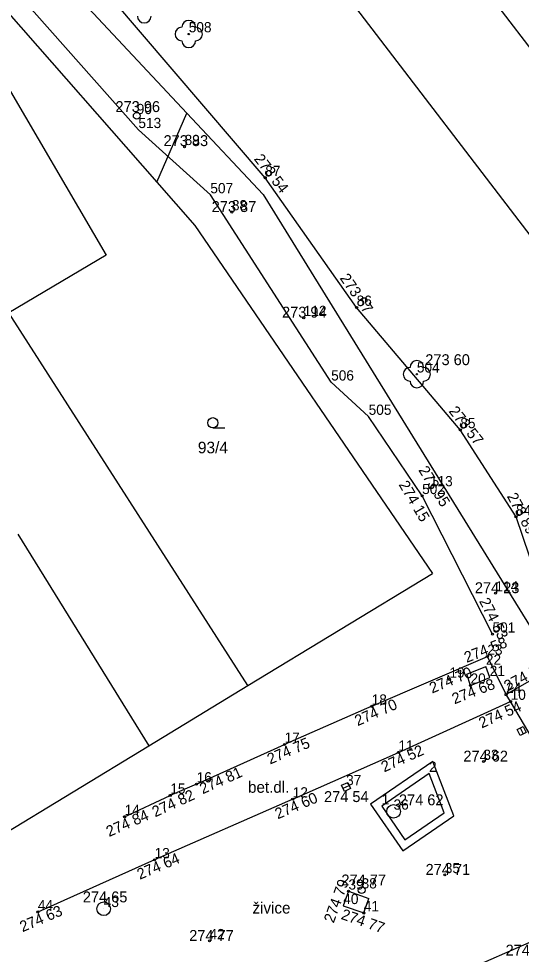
# Model space of a CAD drawing. Extents: x -492379 to -491966, y -1126153 to -1125860.
# Drawn here: x -492207.01 to -492184.88, y -1126038.78 to -1125997.58 of the extents above; entities that cross this region are included whole.
import ezdxf

# ---------------------------------------------------------------- set-up
doc = ezdxf.new("R2010")
doc.units = 0
for name, color, linetype in [('body', 7, 'Continuous'), ('hrana svahu', 7, 'Continuous'), ('kanalizace', 7, 'Continuous'), ('katastrální mapa', 7, 'Continuous'), ('ostatní objekty', 7, 'Continuous'), ('plot', 7, 'Continuous'), ('plyn', 7, 'Continuous'), ('podrobný výškový bod', 7, 'Continuous'), ('popis ploch', 7, 'Continuous'), ('rozhraní ploch', 7, 'Continuous'), ('silové vedení', 7, 'Continuous'), ('vodovod', 7, 'Continuous'), ('vstup na pozemek', 7, 'Continuous'), ('výšky', 7, 'Continuous'), ('čísla bodů', 7, 'Continuous')]:
    doc.layers.add(name, color=color, linetype=linetype)

msp = doc.modelspace()

# ---------------------------------------------------------------- linework, layer by layer
at = {"layer": 'body'}
for p, q in [((-492199.521, -1125998.258), (-492199.521, -1125998.258)), ((-492201.81, -1126001.858), (-492201.81, -1126001.858)), ((-492201.739, -1126002.474), (-492201.739, -1126002.474)), ((-492199.703, -1126003.222), (-492199.703, -1126003.222)), ((-492196.15, -1126004.585), (-492196.15, -1126004.585)), ((-492198.57, -1126005.345), (-492198.57, -1126005.345)), ((-492197.621, -1126006.096), (-492197.621, -1126006.096)), ((-492192.127, -1126010.3), (-492192.127, -1126010.3)), ((-492194.458, -1126010.749), (-492194.458, -1126010.749)), ((-492189.476, -1126013.237), (-492189.476, -1126013.237)), ((-492193.25, -1126013.59), (-492193.25, -1126013.59)), ((-492191.598, -1126015.101), (-492191.598, -1126015.101)), ((-492187.562, -1126015.688), (-492187.562, -1126015.688)), ((-492188.9, -1126018.244), (-492188.9, -1126018.244)), ((-492189.244, -1126018.589), (-492189.244, -1126018.589)), ((-492185.109, -1126019.52), (-492185.109, -1126019.52)), ((-492186.014, -1126022.877), (-492186.014, -1126022.877)), ((-492186.144, -1126024.687), (-492186.144, -1126024.687)), ((-492186.372, -1126025.666), (-492186.372, -1126025.666)), ((-492186.436, -1126026.104), (-492186.436, -1126026.104)), ((-492188.042, -1126026.672), (-492188.042, -1126026.672)), ((-492186.267, -1126026.598), (-492186.267, -1126026.598)), ((-492187.113, -1126026.937), (-492187.113, -1126026.937)), ((-492185.549, -1126027.345), (-492185.549, -1126027.345)), ((-492191.463, -1126027.86), (-492191.463, -1126027.86)), ((-492185.346, -1126027.649), (-492185.346, -1126027.649)), ((-492195.302, -1126029.538), (-492195.302, -1126029.538)), ((-492190.287, -1126029.887), (-492190.287, -1126029.887)), ((-492186.545, -1126030.293), (-492186.545, -1126030.293)), ((-492188.938, -1126030.823), (-492188.938, -1126030.823)), ((-492199.175, -1126031.285), (-492199.175, -1126031.285)), ((-492192.591, -1126031.407), (-492192.591, -1126031.407)), ((-492200.334, -1126031.781), (-492200.334, -1126031.781)), ((-492194.943, -1126031.947), (-492194.943, -1126031.947)), ((-492191.025, -1126032.254), (-492191.025, -1126032.254)), ((-492202.345, -1126032.721), (-492202.345, -1126032.721)), ((-492190.503, -1126032.485), (-492190.503, -1126032.485)), ((-492201.024, -1126034.624), (-492201.024, -1126034.624)), ((-492188.245, -1126035.281), (-492188.245, -1126035.281)), ((-492192.488, -1126036.005), (-492192.488, -1126036.005)), ((-492191.908, -1126035.954), (-492191.908, -1126035.954)), ((-492206.166, -1126036.917), (-492206.166, -1126036.917)), ((-492203.265, -1126036.774), (-492203.265, -1126036.774)), ((-492192.717, -1126036.642), (-492192.717, -1126036.642)), ((-492191.812, -1126036.96), (-492191.812, -1126036.96)), ((-492198.61, -1126038.189), (-492198.61, -1126038.189))]:
    msp.add_line(p, q, dxfattribs=at)
at = {"layer": 'hrana svahu'}
for p, q in [((-492196.15, -1126004.585), (-492205.259, -1125993.96)), ((-492192.127, -1126010.3), (-492196.15, -1126004.585)), ((-492187.562, -1126015.688), (-492192.127, -1126010.3)), ((-492185.109, -1126019.52), (-492187.562, -1126015.688)), ((-492183.695, -1126023.691), (-492185.109, -1126019.52))]:
    msp.add_line(p, q, dxfattribs=at)
at = {"layer": 'kanalizace'}
for p, q in [((-492184.929, -1126028.814), (-492184.787, -1126029.078)), ((-492192.728, -1126031.468), (-492192.454, -1126031.346))]:
    msp.add_line(p, q, dxfattribs=at)
for points in [[(-492184.797, -1126028.743), (-492184.655, -1126029.008), (-492184.92, -1126029.149), (-492185.062, -1126028.885)], [(-492192.789, -1126031.331), (-492192.515, -1126031.209), (-492192.393, -1126031.483), (-492192.667, -1126031.605)]]:
    msp.add_lwpolyline(points, close=True, dxfattribs=at)
for centre in [(-492190.503, -1126032.485), (-492203.265, -1126036.774)]:
    msp.add_circle(centre, 0.3, dxfattribs=at)
at = {"layer": 'katastrální mapa'}
for p, q in [((-492216.8, -1125983.38), (-492199.61, -1126001.74)), ((-492194.65, -1125985.54), (-492177.26, -1126008.38)), ((-492198.1, -1125989.34), (-492176.36, -1126017.77)), ((-492207.54, -1125997.23), (-492200.93, -1126004.78)), ((-492208.65, -1125998.64), (-492203.15, -1126007.99)), ((-492200.93, -1126004.78), (-492199.61, -1126001.74)), ((-492199.61, -1126001.74), (-492196.25, -1126005.33)), ((-492200.93, -1126004.78), (-492199.25, -1126006.69)), ((-492196.25, -1126005.33), (-492184.32, -1126024.61)), ((-492199.25, -1126006.69), (-492188.79, -1126022.01)), ((-492203.15, -1126007.99), (-492207.44, -1126010.54)), ((-492196.92, -1126026.95), (-492207.44, -1126010.54)), ((-492198.46, -1126015.6), (-492197.93, -1126015.6)), ((-492207.05, -1126020.28), (-492201.28, -1126029.6)), ((-492196.92, -1126026.95), (-492188.79, -1126022.01)), ((-492201.28, -1126029.6), (-492196.92, -1126026.95)), ((-492212.92, -1126036.68), (-492201.28, -1126029.6)), ((-492191.74, -1126041.4), (-492182.01, -1126037.16))]:
    msp.add_line(p, q, dxfattribs=at)
msp.add_circle((-492198.46, -1126015.375), 0.225, dxfattribs=at)
at = {"layer": 'ostatní objekty'}
for p, q in [((-492188.77, -1126030.283), (-492191.512, -1126032.163)), ((-492187.851, -1126032.684), (-492188.77, -1126030.283)), ((-492188.938, -1126030.823), (-492191.025, -1126032.254)), ((-492188.277, -1126032.551), (-492188.938, -1126030.823)), ((-492191.512, -1126032.163), (-492190.098, -1126034.225)), ((-492191.025, -1126032.254), (-492190.007, -1126033.738)), ((-492190.098, -1126034.225), (-492187.851, -1126032.684)), ((-492190.007, -1126033.738), (-492188.277, -1126032.551))]:
    msp.add_line(p, q, dxfattribs=at)
for centre in [(-492199.521, -1125998.258), (-492189.476, -1126013.237)]:
    msp.add_circle(centre, 0.03, dxfattribs=at)
for centre, start, end in [((-492201.482, -1125997.469), 180, 0), ((-492199.521, -1125997.958), 0, 180), ((-492199.821, -1125998.258), 90, 270), ((-492199.221, -1125998.258), 270, 90), ((-492199.521, -1125998.558), 180, 0), ((-492189.476, -1126012.937), 0, 180), ((-492189.776, -1126013.237), 90, 270), ((-492189.176, -1126013.237), 270, 90), ((-492189.476, -1126013.537), 180, 0)]:
    msp.add_arc(centre, 0.3, start, end, dxfattribs=at)
at = {"layer": 'plot'}
for p, q in [((-492201.739, -1126002.474), (-492206.915, -1125996.619)), ((-492198.57, -1126005.345), (-492201.739, -1126002.474)), ((-492193.25, -1126013.59), (-492198.57, -1126005.345)), ((-492191.598, -1126015.101), (-492193.25, -1126013.59)), ((-492189.244, -1126018.589), (-492191.598, -1126015.101)), ((-492186.144, -1126024.687), (-492189.244, -1126018.589)), ((-492191.463, -1126027.86), (-492186.372, -1126025.666)), ((-492199.175, -1126031.285), (-492195.302, -1126029.538)), ((-492202.345, -1126032.721), (-492200.334, -1126031.781))]:
    msp.add_line(p, q, dxfattribs=at)
at = {"layer": 'plyn'}
msp.add_circle((-492201.81, -1126001.858), 0.15, dxfattribs=at)
at = {"layer": 'podrobný výškový bod'}
for centre in [(-492199.703, -1126003.222), (-492196.15, -1126004.585), (-492197.621, -1126006.096), (-492192.127, -1126010.3), (-492194.458, -1126010.749), (-492187.562, -1126015.688), (-492188.9, -1126018.244), (-492189.244, -1126018.589), (-492185.109, -1126019.52), (-492186.014, -1126022.877), (-492186.144, -1126024.687), (-492186.372, -1126025.666), (-492188.042, -1126026.672), (-492187.113, -1126026.937), (-492185.549, -1126027.345), (-492191.463, -1126027.86), (-492185.346, -1126027.649), (-492195.302, -1126029.538), (-492190.287, -1126029.887), (-492186.545, -1126030.293), (-492199.175, -1126031.285), (-492200.334, -1126031.781), (-492194.943, -1126031.947), (-492202.345, -1126032.721), (-492201.024, -1126034.624), (-492188.245, -1126035.281), (-492192.488, -1126036.005), (-492206.166, -1126036.917), (-492191.812, -1126036.96), (-492198.61, -1126038.189)]:
    msp.add_circle(centre, 0.045, dxfattribs=at)
at = {"layer": 'rozhraní ploch'}
for p, q in [((-492182.164, -1126025.391), (-492185.549, -1126027.345)), ((-492185.549, -1126027.345), (-492186.372, -1126025.666)), ((-492185.346, -1126027.649), (-492185.549, -1126027.345)), ((-492190.287, -1126029.887), (-492185.346, -1126027.649)), ((-492183.251, -1126031.227), (-492185.346, -1126027.649)), ((-492194.943, -1126031.947), (-492190.287, -1126029.887)), ((-492194.943, -1126031.947), (-492201.024, -1126034.624)), ((-492201.024, -1126034.624), (-492206.166, -1126036.917))]:
    msp.add_line(p, q, dxfattribs=at)
at = {"layer": 'silové vedení'}
for p, q in [((-492187.282, -1126026.443), (-492186.436, -1126026.104)), ((-492186.267, -1126026.598), (-492186.436, -1126026.104)), ((-492187.113, -1126026.937), (-492187.282, -1126026.443)), ((-492187.113, -1126026.937), (-492186.267, -1126026.598))]:
    msp.add_line(p, q, dxfattribs=at)
at = {"layer": 'vodovod'}
for p, q in [((-492192.488, -1126036.005), (-492192.717, -1126036.642)), ((-492192.488, -1126036.005), (-492191.588, -1126036.321)), ((-492191.812, -1126036.96), (-492191.588, -1126036.321)), ((-492192.717, -1126036.642), (-492191.812, -1126036.96))]:
    msp.add_line(p, q, dxfattribs=at)
msp.add_circle((-492191.908, -1126035.954), 0.15, dxfattribs=at)
at = {"layer": 'vstup na pozemek'}
for p, q in [((-492191.463, -1126027.86), (-492195.302, -1126029.538)), ((-492199.175, -1126031.285), (-492200.334, -1126031.781))]:
    msp.add_line(p, q, dxfattribs=at)

# ---------------------------------------------------------------- texts
at = {"layer": 'katastrální mapa'}
msp.add_text('93/4', height=0.51, dxfattribs=at).set_placement((-492199.12, -1126016.72))
at = {"layer": 'popis ploch'}
for s, p in [('bet.dl.', (-492196.91, -1126031.667)), ('živice', (-492196.713, -1126036.984))]:
    msp.add_text(s, height=0.5, dxfattribs=at).set_placement(p)
at = {"layer": 'výšky'}
for s, p in [('273 96', (-492202.749, -1126001.694)), ('273 83', (-492200.63, -1126003.193)), ('273 87', (-492198.511, -1126006.096)), ('273 94', (-492195.413, -1126010.746)), ('273 60', (-492189.104, -1126012.838)), ('274 23', (-492186.923, -1126022.878)), ('274 62', (-492187.427, -1126030.293)), ('274 54', (-492193.564, -1126032.075)), ('274 62', (-492190.264, -1126032.218)), ('274 71', (-492189.091, -1126035.281)), ('274 77', (-492192.798, -1126035.747)), ('274 65', (-492204.186, -1126036.493)), ('274 77', (-492199.5, -1126038.189)), ('274 73', (-492185.567, -1126038.835))]:
    msp.add_text(s, height=0.48, dxfattribs=at).set_placement(p)
for s, rotation, p in [('273 54', 307.94, (-492196.671, -1126003.765)), ('273 67', 305.0253, (-492192.89, -1126009.009)), ('273 57', 308.2492, (-492188.095, -1126014.872)), ('273 95', 301.7497, (-492189.422, -1126017.458)), ('274 15', 300.5855, (-492190.292, -1126018.096)), ('273 89', 298.1924, (-492185.522, -1126018.61)), ('274 53', 296.9149, (-492186.743, -1126023.225)), ('274 58', 21.5177, (-492187.278, -1126025.95)), ('274 70', 22.7225, (-492188.802, -1126027.3)), ('274 54', 28.5451, (-492185.477, -1126027.214)), ('274 68', 21.1447, (-492187.82, -1126027.774)), ('274 70', 23.8541, (-492192.086, -1126028.74)), ('274 54', 24.0904, (-492186.617, -1126028.838)), ('274 75', 23.327, (-492195.94, -1126030.428)), ('274 52', 24.1679, (-492190.914, -1126030.772)), ('274 81', 24.1428, (-492198.91, -1126031.737)), ('274 82', 24.6097, (-492201.001, -1126032.752)), ('274 60', 23.2131, (-492195.6, -1126032.839)), ('274 84', 23.7682, (-492203.03, -1126033.619)), ('274 64', 23.0399, (-492201.676, -1126035.5)), ('274 79', 69.9339, (-492193.14, -1126037.43)), ('274 63', 23.0481, (-492206.841, -1126037.809)), ('274 77', 340.6357, (-492192.849, -1126037.214))]:
    msp.add_text(s, height=0.48, rotation=rotation, dxfattribs=at).set_placement(p)
at = {"layer": 'čísla bodů'}
for s, p in [('508', (-492199.521, -1125998.183)), ('90', (-492201.81, -1126001.783)), ('513', (-492201.739, -1126002.399)), ('89', (-492199.703, -1126003.147)), ('87', (-492196.15, -1126004.51)), ('507', (-492198.57, -1126005.27)), ('88', (-492197.621, -1126006.021)), ('86', (-492192.127, -1126010.225)), ('112', (-492194.458, -1126010.674)), ('506', (-492193.25, -1126013.515)), ('504', (-492189.476, -1126013.162)), ('505', (-492191.598, -1126015.026)), ('85', (-492187.562, -1126015.613)), ('113', (-492188.9, -1126018.169)), ('502', (-492189.244, -1126018.514)), ('84', (-492185.109, -1126019.445)), ('114', (-492186.014, -1126022.802)), ('501', (-492186.144, -1126024.612)), ('23', (-492186.372, -1126025.591)), ('22', (-492186.436, -1126026.029)), ('19', (-492188.042, -1126026.597)), ('21', (-492186.267, -1126026.523)), ('20', (-492187.113, -1126026.862)), ('24', (-492185.549, -1126027.27)), ('18', (-492191.463, -1126027.785)), ('10', (-492185.346, -1126027.574)), ('17', (-492195.302, -1126029.463)), ('11', (-492190.287, -1126029.812)), ('33', (-492186.545, -1126030.218)), ('2', (-492188.938, -1126030.748)), ('16', (-492199.175, -1126031.21)), ('37', (-492192.591, -1126031.332)), ('15', (-492200.334, -1126031.706)), ('12', (-492194.943, -1126031.872)), ('1', (-492191.025, -1126032.179)), ('36', (-492190.503, -1126032.41)), ('14', (-492202.345, -1126032.646)), ('13', (-492201.024, -1126034.549)), ('35', (-492188.245, -1126035.206)), ('39', (-492192.488, -1126035.93)), ('38', (-492191.908, -1126035.879)), ('40', (-492192.717, -1126036.567)), ('44', (-492206.166, -1126036.842)), ('43', (-492203.265, -1126036.699)), ('41', (-492191.812, -1126036.885)), ('42', (-492198.61, -1126038.114))]:
    msp.add_text(s, height=0.45, dxfattribs=at).set_placement(p)

doc.saveas('drawing.dxf')
